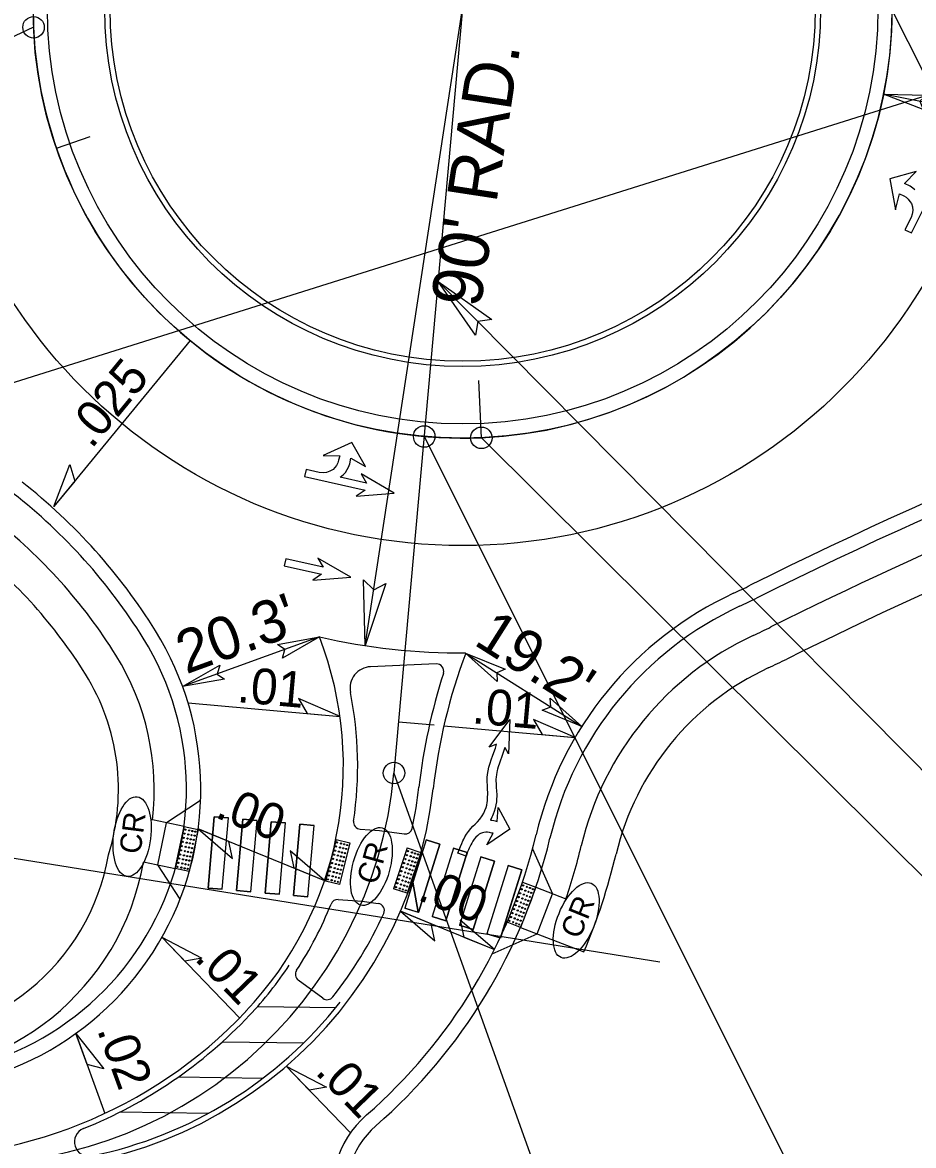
# Model space of a CAD drawing. Extents: x 2010838 to 2015151, y 441905 to 447792.
# Drawn here: x 2013126.8 to 2013251.3, y 444759.6 to 444916.5 of the extents above; entities that cross this region are included whole.
import ezdxf

# ---------------------------------------------------------------- set-up
doc = ezdxf.new("R2010")
doc.units = 0
for name, color, linetype in [('A-Wall-Abov', 7, 'Continuous'), ('A-Wall-Blow', 7, 'Continuous'), ('A-Wall-Comp', 7, 'Continuous'), ('C-Alignment Geometry', 7, 'Continuous'), ('C-Building', 7, 'Continuous'), ('C-CURB STOPS', 7, 'Continuous'), ('C-EOP 1', 7, 'Continuous'), ('C-Grave Plots', 7, 'Continuous'), ('CLRD', 7, 'Continuous'), ('DEED', 7, 'Continuous'), ('Default_10ft_LIDAR_Contou', 7, 'Continuous'), ('HATCH', 7, 'Continuous'), ('s-Existing Major', 7, 'Continuous'), ('S-Existing Minor', 7, 'Continuous'), ('S-overhead electric', 7, 'Continuous'), ('TEXT-LG', 7, 'Continuous'), ('TEXT-MED', 7, 'Continuous'), ('X3', 7, 'Continuous'), ('X4', 7, 'Continuous')]:
    doc.layers.add(name, color=color, linetype=linetype)

msp = doc.modelspace()

# ---------------------------------------------------------------- linework, layer by layer
at = {"layer": 'A-Wall-Abov'}
msp.add_lwpolyline([(2013251.45, 444893.1), (2013251.16, 444893.34), (2013250.77, 444893.6), (2013250.02, 444893.95), (2013251.63, 444895.67), (2013247.94, 444894.62), (2013248.76, 444890.3), (2013249.32, 444892.54), (2013249.89, 444892.23), (2013250.23, 444892.05), (2013250.53, 444891.79), (2013250.75, 444891.48), (2013250.97, 444891.16), (2013251.11, 444890.69), (2013251.14, 444890.19), (2013251.08, 444889.71), (2013250.92, 444889.2), (2013250.06, 444887.5), (2013250.96, 444887.06), (2013254.83, 444894.81)], dxfattribs=at)
for points in [[(2013166.18, 444853.06), (2013174.64, 444851.14), (2013173.42, 444850.31), (2013178.73, 444850.73), (2013174.12, 444853.4), (2013174.86, 444852.12), (2013171.18, 444852.95), (2013171.64, 444853.32), (2013171.92, 444853.62), (2013172.17, 444854.02), (2013172.33, 444854.36), (2013172.5, 444854.8), (2013172.66, 444855.61), (2013174.71, 444854.46), (2013172.81, 444857.79), (2013168.81, 444855.97), (2013171.11, 444855.96), (2013170.96, 444855.33), (2013170.86, 444854.96), (2013170.68, 444854.6), (2013170.43, 444854.31), (2013170.17, 444854.03), (2013169.75, 444853.78), (2013169.28, 444853.62), (2013168.79, 444853.57), (2013168.25, 444853.61), (2013166.41, 444854.03)], [(2013168.05, 444841.66), (2013168.78, 444840.38), (2013163.59, 444841.57), (2013163.36, 444840.59), (2013168.56, 444839.41), (2013167.35, 444838.57), (2013172.65, 444838.99)], [(2013194.89, 444819.09), (2013194.69, 444814.3), (2013194.2, 444815.17), (2013194.18, 444815.2), (2013193.73, 444813.95), (2013193.51, 444813.31), (2013193.41, 444813.01), (2013193.24, 444812.49), (2013193.15, 444812.18), (2013193.09, 444811.98), (2013192.99, 444811.44), (2013192.95, 444811.07), (2013192.93, 444810.8), (2013192.93, 444810.51), (2013192.94, 444810.18), (2013192.95, 444809.98), (2013192.96, 444809.68), (2013193.03, 444809.09), (2013193.05, 444808.66), (2013193.04, 444808.35), (2013193.03, 444808.05), (2013192.99, 444807.6), (2013192.93, 444807.21), (2013192.83, 444806.74), (2013192.7, 444806.28), (2013192.56, 444805.91), (2013192.45, 444805.64), (2013192.35, 444805.45), (2013192.15, 444805.07), (2013192.34, 444805.05), (2013192.63, 444805), (2013192.81, 444804.96), (2013193.1, 444804.89), (2013193.22, 444806.82), (2013194.87, 444803.8), (2013191.66, 444801.61), (2013192.52, 444803.22), (2013192.34, 444803.26), (2013192.03, 444803.33), (2013191.76, 444803.37), (2013191.51, 444803.38), (2013191.26, 444803.35), (2013191.05, 444803.3), (2013190.75, 444803.17), (2013190.59, 444803.08), (2013190.39, 444802.93), (2013190.1, 444802.66), (2013189.91, 444802.4), (2013189.72, 444802.11), (2013189.56, 444801.86), (2013189.43, 444801.62), (2013189.28, 444801.33), (2013189.19, 444801.14), (2013189.09, 444800.92), (2013188.98, 444800.65), (2013188.9, 444800.43), (2013188.81, 444800.17), (2013188.77, 444800.04), (2013187.61, 444800.45), (2013187.79, 444800.93), (2013187.97, 444801.37), (2013188.15, 444801.78), (2013188.32, 444802.16), (2013188.45, 444802.42), (2013188.6, 444802.72), (2013188.83, 444803.09), (2013189.11, 444803.49), (2013189.4, 444803.87), (2013189.72, 444804.2), (2013190.03, 444804.49), (2013190.36, 444804.84), (2013190.66, 444805.2), (2013191.01, 444805.68), (2013191.23, 444806.04), (2013191.4, 444806.39), (2013191.55, 444806.8), (2013191.65, 444807.16), (2013191.72, 444807.5), (2013191.75, 444807.74), (2013191.77, 444808.12), (2013191.78, 444808.81), (2013191.76, 444809.44), (2013191.73, 444810.01), (2013191.7, 444810.37), (2013191.69, 444810.55), (2013191.7, 444811.02), (2013191.74, 444811.45), (2013191.83, 444811.95), (2013191.95, 444812.46), (2013192.11, 444813), (2013192.27, 444813.48), (2013192.49, 444814.12), (2013192.85, 444815.12), (2013193.03, 444815.66), (2013192, 444815.26)]]:
    msp.add_lwpolyline(points, close=True, dxfattribs=at)
at = {"layer": 'A-Wall-Blow'}
for p, q in [((2013150.2, 444872.03), (2013131.16, 444848.84)), ((2013149.92, 444821.44), (2013171.15, 444819.53)), ((2013185.65, 444818.23), (2013203.98, 444816.58)), ((2013151.33, 444803.82), (2013168.99, 444796.64)), ((2013179.59, 444792.33), (2013192.71, 444786.99)), ((2013146.27, 444788.69), (2013157.12, 444777.44)), ((2013134.23, 444775.25), (2013138.31, 444764.1)), ((2013163.64, 444770.69), (2013172.61, 444761.39))]:
    msp.add_line(p, q, dxfattribs=at)
at = {"layer": 'A-Wall-Comp'}
for points in [[(2013131.16, 444848.84), (2013133.43, 444854.75), (2013134.1, 444852.42)], [(2013171.15, 444819.53), (2013165.35, 444822.06), (2013166.54, 444819.95)], [(2013203.98, 444816.58), (2013198.18, 444819.11), (2013199.37, 444817)], [(2013151.33, 444803.82), (2013156.14, 444799.71), (2013155.62, 444802.08)], [(2013168.99, 444796.64), (2013164.18, 444800.75), (2013164.7, 444798.38)], [(2013179.59, 444792.33), (2013184.39, 444788.21), (2013183.87, 444790.58)], [(2013192.71, 444786.99), (2013187.91, 444791.1), (2013188.43, 444788.73)], [(2013146.27, 444788.69), (2013151.87, 444785.76), (2013149.48, 444785.36)], [(2013134.23, 444775.25), (2013138.17, 444770.31), (2013135.82, 444770.91)], [(2013163.64, 444770.69), (2013169.25, 444767.76), (2013166.85, 444767.36)]]:
    msp.add_lwpolyline(points, close=True, dxfattribs=at)
at = {"layer": 'C-Alignment Geometry'}
for p, q in [((2013159.66, 444779.05), (2013170.58, 444778.91)), ((2013154.74, 444774.11), (2013166.1, 444773.97)), ((2013148.58, 444769.2), (2013160.41, 444769.04)), ((2013140.44, 444764.3), (2013152.83, 444764.14))]:
    msp.add_line(p, q, dxfattribs=at)
for centre, radius, start, end in [((2013121.62, 444812.65), 50.75, 316.6324, 326.7514), ((2013124.54, 444816.2), 59.25, 281.6024, 321.882), ((2013110.72, 444822.95), 65.75, 291.9588, 316.6324), ((2013136.05, 444760.12), 2, 111.9588, 281.6024)]:
    msp.add_arc(centre, radius, start, end, dxfattribs=at)
at = {"layer": 'C-Building'}
for p, q in [((2013131.54, 444898.89), (2013136.27, 444900.52)), ((2013179.34, 444818.8), (2013184.32, 444818.35))]:
    msp.add_line(p, q, dxfattribs=at)
at = {"layer": 'C-CURB STOPS'}
for p, q in [((2013184.6, 444826.87), (2013175.42, 444826.47)), ((2013173.97, 444803.79), (2013176.67, 444803.6)), ((2013176.67, 444803.6), (2013180.11, 444803.13)), ((2013170.9, 444793.97), (2013174.25, 444793.75)), ((2013174.25, 444793.75), (2013176.49, 444793.43)), ((2013168.77, 444780.18), (2013165.31, 444782.73))]:
    msp.add_line(p, q, dxfattribs=at)
msp.add_circle((2013188.28, 444918.4), 58, dxfattribs=at)
for centre, radius, start, end in [((2013184.64, 444825.87), 1, 342.1406, 92.4521), ((2013175.55, 444823.48), 3, 92.4521, 191.35), ((2013263.65, 444800.41), 82, 162.1406, 173.5264), ((2013121.62, 444812.65), 52, 351.464, 11.35), ((2013124.54, 444816.2), 58, 347.7647, 353.5264), ((2013174.04, 444804.79), 1, 171.464, 266.1176), ((2013180.24, 444804.12), 1, 262.0911, 347.7647), ((2013170.83, 444792.97), 1, 86.1176, 158.2062), ((2013121.62, 444812.65), 52, 326.6756, 338.2062), ((2013176.35, 444792.44), 1, 335.3711, 82.0911), ((2013124.54, 444816.2), 58, 321.8457, 335.3711), ((2013165.91, 444783.53), 1, 146.6756, 233.5385), ((2013169.36, 444780.98), 1, 233.5385, 321.8457)]:
    msp.add_arc(centre, radius, start, end, dxfattribs=at)
at = {"layer": 'C-EOP 1'}
msp.add_line((2013190.89, 444858.45), (2013190.54, 444866.45), dxfattribs=at)
at = {"layer": 'CLRD'}
msp.add_line((2013188.28, 444918.4), (2013178.69, 444811.64), dxfattribs=at)
for centre, start, end in [((2013188.28, 444918.4), 92.4922, 182.4922), ((2013188.28, 444918.4), 272.4922, 2.4922), ((2013188.28, 444918.4), 182.4922, 272.4922), ((2013118.93, 444817), 266.9102, 354.8697)]:
    msp.add_arc(centre, 60, start, end, dxfattribs=at)
at = {"layer": 'DEED'}
for radius in [50, 49.25]:
    msp.add_circle((2013188.28, 444918.4), radius, dxfattribs=at)
at = {"layer": 'Default_10ft_LIDAR_Contou'}
for p, q in [((2013248.28, 444918.14), (2013322.3, 444771.2)), ((2013128.34, 444915.79), (2012938.22, 444827.44)), ((2013184.86, 444880.3), (2013338.65, 444724.98)), ((2013182.91, 444858.64), (2013267.89, 444688.86)), ((2013190.89, 444858.45), (2013335.72, 444714.48)), ((2013178.69, 444811.64), (2013247.53, 444618.89))]:
    msp.add_line(p, q, dxfattribs=at)
for centre in [(2013128.34, 444915.79), (2013182.91, 444858.64), (2013190.89, 444858.45), (2013190.89, 444858.45), (2013178.69, 444811.64)]:
    msp.add_circle(centre, 1.5, dxfattribs=at)
at = {"layer": 'HATCH'}
for p, q in [((2013188.7, 444828.4), (2013204.92, 444818.13)), ((2013152.71, 444795.57), (2013153.58, 444805.53)), ((2013153.58, 444805.53), (2013152.72, 444795.57)), ((2013153.58, 444805.53), (2013155.57, 444805.36)), ((2013155.57, 444805.36), (2013153.58, 444805.53)), ((2013154.71, 444795.4), (2013155.57, 444805.36)), ((2013154.71, 444795.4), (2013155.57, 444805.36)), ((2013156.7, 444795.23), (2013157.56, 444805.19)), ((2013157.56, 444805.19), (2013156.7, 444795.23)), ((2013157.56, 444805.19), (2013159.56, 444805.01)), ((2013159.56, 444805.01), (2013157.56, 444805.19)), ((2013158.69, 444795.05), (2013159.56, 444805.01)), ((2013158.69, 444795.05), (2013159.56, 444805.01)), ((2013160.68, 444794.88), (2013161.55, 444804.84)), ((2013161.55, 444804.84), (2013160.68, 444794.88)), ((2013161.55, 444804.84), (2013163.54, 444804.67)), ((2013163.54, 444804.67), (2013161.55, 444804.84)), ((2013162.68, 444794.71), (2013163.54, 444804.67)), ((2013162.68, 444794.71), (2013163.54, 444804.67)), ((2013164.67, 444794.53), (2013165.53, 444804.5)), ((2013165.53, 444804.5), (2013164.67, 444794.53)), ((2013165.53, 444804.5), (2013167.53, 444804.32)), ((2013167.53, 444804.32), (2013165.53, 444804.5)), ((2013166.66, 444794.36), (2013167.53, 444804.32)), ((2013166.66, 444794.36), (2013167.53, 444804.32)), ((2013183.2, 444802.32), (2013180.21, 444792.78)), ((2013183.2, 444802.32), (2013181.34, 444796.38)), ((2013185.11, 444801.72), (2013182.11, 444792.18)), ((2013182.11, 444792.18), (2013185.11, 444801.72)), ((2013183.2, 444802.32), (2013185.11, 444801.72)), ((2013185.11, 444801.72), (2013183.2, 444802.32)), ((2013187.02, 444801.12), (2013184.02, 444791.58)), ((2013187.02, 444801.12), (2013184.03, 444791.6)), ((2013188.93, 444800.52), (2013185.93, 444790.98)), ((2013185.93, 444790.98), (2013188.93, 444800.52)), ((2013187.02, 444801.12), (2013188.93, 444800.52)), ((2013188.93, 444800.52), (2013187.02, 444801.12)), ((2013190.84, 444799.92), (2013187.84, 444790.38)), ((2013190.84, 444799.92), (2013187.84, 444790.38)), ((2013190.84, 444799.92), (2013192.74, 444799.33)), ((2013192.74, 444799.33), (2013190.84, 444799.92)), ((2013192.74, 444799.33), (2013189.75, 444789.78)), ((2013189.75, 444789.78), (2013192.74, 444799.33)), ((2013194.65, 444798.73), (2013191.66, 444789.19)), ((2013194.65, 444798.73), (2013191.66, 444789.19)), ((2013194.65, 444798.73), (2013196.56, 444798.13)), ((2013196.56, 444798.13), (2013194.65, 444798.73)), ((2013196.56, 444798.13), (2013193.56, 444788.59)), ((2013193.72, 444789.09), (2013196.56, 444798.13)), ((2013154.71, 444795.4), (2013152.72, 444795.57)), ((2013152.72, 444795.57), (2013154.71, 444795.4)), ((2013158.69, 444795.05), (2013156.7, 444795.23)), ((2013156.7, 444795.23), (2013158.69, 444795.05)), ((2013181.34, 444796.38), (2013180.21, 444792.78)), ((2013181.34, 444796.38), (2013182.06, 444792.2)), ((2013182.06, 444792.2), (2013181.34, 444796.38)), ((2013162.68, 444794.71), (2013160.68, 444794.88)), ((2013160.68, 444794.88), (2013162.68, 444794.71)), ((2013166.66, 444794.36), (2013164.67, 444794.53)), ((2013164.67, 444794.53), (2013166.66, 444794.36)), ((2013182.11, 444792.18), (2013180.21, 444792.78)), ((2013180.21, 444792.78), (2013182.06, 444792.2)), ((2013182.06, 444792.2), (2013182.11, 444792.18)), ((2013185.93, 444790.98), (2013184.03, 444791.6)), ((2013184.03, 444791.6), (2013185.93, 444790.98)), ((2013189.75, 444789.78), (2013187.84, 444790.38)), ((2013187.84, 444790.38), (2013189.75, 444789.78)), ((2013193.56, 444788.59), (2013191.66, 444789.19)), ((2013191.66, 444789.19), (2013193.5, 444788.61))]:
    msp.add_line(p, q, dxfattribs=at)
msp.add_circle((2013188.28, 444918.4), 75, dxfattribs=at)
msp.add_arc((2013125.58, 444820.42), 75, 334.9004, 335.3097, dxfattribs=at)
at = {"layer": 's-Existing Major'}
for points in [[(2013252.62, 444904.32), (2013247.08, 444906.47), (2013253.05, 444906.32), (2013252.12, 444905.45)], [(2013190.09, 444872.81), (2013184.86, 444880.3), (2013192.36, 444874.99), (2013190.42, 444874.68)], [(2013177.56, 444838.09), (2013174.66, 444829.43), (2013174.45, 444838.62), (2013175.86, 444837.24)], [(2013162.43, 444829.6), (2013168.27, 444830.65), (2013163.1, 444827.66), (2013163.45, 444828.89)], [(2013193.1, 444824.42), (2013188.7, 444828.4), (2013194.23, 444826.13), (2013193.04, 444825.65)], [(2013155.01, 444824.75), (2013149.17, 444823.7), (2013154.34, 444826.69), (2013153.99, 444825.46)], [(2013200.51, 444822.11), (2013204.92, 444818.13), (2013199.39, 444820.4), (2013200.58, 444820.88)]]:
    msp.add_lwpolyline(points, close=True, dxfattribs=at)
at = {"layer": 'S-Existing Minor'}
for p, q in [((2012728, 444741.11), (2013407.25, 444954.8)), ((2013174.66, 444829.43), (2013188.28, 444918.4)), ((2013264.72, 444902.89), (2013247.08, 444906.47)), ((2013168.27, 444830.65), (2013149.17, 444823.7)), ((2013188.7, 444828.4), (2013204.92, 444818.13))]:
    msp.add_line(p, q, dxfattribs=at)
at = {"layer": 'S-overhead electric'}
msp.add_circle((2013188.28, 444918.4), 60, dxfattribs=at)
for centre, radius, start, end in [((2013509.51, 444274.03), 630, 98.35841, 116.49713), ((2013077.42, 444789.28), 80, 31.8625, 51.9343), ((2013188.28, 444918.4), 90, 294.8702, 296.4971), ((2013247.16, 444791.38), 50, 114.8702, 166.5654), ((2013109.7, 444809.34), 42, 266.6924, 31.8625), ((2013121.62, 444812.65), 50, 316.6324, 21.0956), ((2013188.28, 444918.4), 90, 257.155, 270.2673), ((2013263.65, 444800.41), 80, 159.5249, 173.5264), ((2013124.54, 444816.2), 60, 266.9102, 353.5264), ((2013125.58, 444820.42), 75, 311.0732, 346.5651), ((2013110.72, 444822.95), 65, 266.9102, 316.6324), ((2013184.05, 444753.33), 14, 131.0732, 263.7653)]:
    msp.add_arc(centre, radius, start, end, dxfattribs=at)
at = {"layer": 'TEXT-LG'}
for p, q in [((2013151.67, 444807.8), (2013146.91, 444804.67)), ((2013149.36, 444804.16), (2013144.94, 444805.08)), ((2013145.68, 444798.8), (2013146.91, 444804.67)), ((2013149.37, 444804.16), (2013148.14, 444798.29)), ((2013148.14, 444798.29), (2013149.37, 444804.16)), ((2013149.37, 444804.16), (2013151.32, 444803.75)), ((2013151.32, 444803.75), (2013150.1, 444797.88)), ((2013170.59, 444802.37), (2013169.12, 444796.55)), ((2013170.59, 444802.37), (2013172.53, 444801.88)), ((2013172.53, 444801.88), (2013171.06, 444796.06)), ((2013180.54, 444801.17), (2013178.64, 444795.48)), ((2013180.54, 444801.17), (2013182.44, 444800.53)), ((2013182.44, 444800.53), (2013180.54, 444794.84)), ((2013198.04, 444801.06), (2013200.84, 444794.78)), ((2013148.14, 444798.28), (2013143.7, 444799.21)), ((2013148.81, 444794.03), (2013145.68, 444798.8)), ((2013150.1, 444797.88), (2013148.14, 444798.29)), ((2013171.06, 444796.06), (2013169.12, 444796.55)), ((2013180.54, 444794.84), (2013178.64, 444795.48)), ((2013196.63, 444796.39), (2013194.48, 444790.79)), ((2013198.49, 444795.68), (2013196.35, 444790.07)), ((2013196.63, 444796.39), (2013198.49, 444795.68)), ((2013198.49, 444795.68), (2013202.7, 444794.07)), ((2013198.69, 444789.18), (2013200.84, 444794.78)), ((2013196.35, 444790.07), (2013194.48, 444790.79)), ((2013192.4, 444786.37), (2013198.69, 444789.18)), ((2013196.35, 444790.07), (2013205.22, 444786.67))]:
    msp.add_line(p, q, dxfattribs=at)
for centre in [(2013149.42, 444803.17), (2013149.54, 444803.73), (2013149.96, 444803.06), (2013150.08, 444803.63), (2013150.53, 444803.53), (2013150.95, 444803.45), (2013149.05, 444801.43), (2013149.18, 444802.02), (2013149.3, 444802.58), (2013149.72, 444801.91), (2013149.84, 444802.48), (2013150.17, 444801.82), (2013150.29, 444802.38), (2013150.41, 444802.96), (2013150.59, 444801.74), (2013150.71, 444802.3), (2013150.84, 444802.89), (2013170.75, 444801.93), (2013171.29, 444801.8), (2013171.73, 444801.68), (2013172.15, 444801.58), (2013148.81, 444800.25), (2013148.93, 444800.84), (2013149.35, 444800.14), (2013149.48, 444800.73), (2013149.6, 444801.33), (2013149.8, 444800.04), (2013149.93, 444800.63), (2013150.05, 444801.23), (2013150.22, 444799.97), (2013150.35, 444800.55), (2013150.47, 444801.15), (2013170.32, 444800.23), (2013170.46, 444800.79), (2013170.61, 444801.37), (2013170.85, 444800.11), (2013171, 444800.66), (2013171.15, 444801.24), (2013171.3, 444799.99), (2013171.44, 444800.54), (2013171.59, 444801.12), (2013171.72, 444799.89), (2013171.86, 444800.45), (2013172.01, 444801.03), (2013180.48, 444800.18), (2013180.66, 444800.72), (2013181.01, 444800.01), (2013181.19, 444800.55), (2013181.44, 444799.86), (2013181.62, 444800.4), (2013182.04, 444800.27), (2013148.45, 444798.54), (2013148.57, 444799.1), (2013148.69, 444799.69), (2013148.99, 444798.43), (2013149.11, 444799), (2013149.23, 444799.58), (2013149.44, 444798.33), (2013149.56, 444798.9), (2013149.68, 444799.48), (2013149.98, 444798.82), (2013150.11, 444799.41), (2013169.87, 444798.48), (2013170.02, 444799.06), (2013170.17, 444799.65), (2013170.41, 444798.35), (2013170.56, 444798.93), (2013170.71, 444799.52), (2013171, 444798.81), (2013171.15, 444799.41), (2013171.42, 444798.72), (2013171.57, 444799.31), (2013179.91, 444798.49), (2013180.1, 444799.06), (2013180.29, 444799.61), (2013180.44, 444798.33), (2013180.63, 444798.9), (2013180.81, 444799.44), (2013181.07, 444798.74), (2013181.25, 444799.29), (2013181.48, 444798.62), (2013181.66, 444799.16), (2013181.85, 444799.73), (2013149.86, 444798.26), (2013169.44, 444796.79), (2013169.58, 444797.34), (2013169.73, 444797.92), (2013170.12, 444797.21), (2013170.27, 444797.8), (2013170.56, 444797.1), (2013170.71, 444797.68), (2013170.85, 444798.23), (2013170.98, 444797), (2013171.13, 444797.58), (2013171.27, 444798.14), (2013179.35, 444796.8), (2013179.53, 444797.35), (2013179.72, 444797.92), (2013180.06, 444797.18), (2013180.25, 444797.75), (2013180.49, 444797.03), (2013180.68, 444797.6), (2013180.87, 444798.18), (2013180.9, 444796.9), (2013181.09, 444797.47), (2013181.28, 444798.05), (2013169.98, 444796.66), (2013170.42, 444796.54), (2013170.84, 444796.44), (2013178.97, 444795.69), (2013179.15, 444796.24), (2013179.5, 444795.52), (2013179.68, 444796.07), (2013179.87, 444796.64), (2013179.93, 444795.37), (2013180.12, 444795.92), (2013180.31, 444796.48), (2013180.34, 444795.25), (2013180.53, 444795.79), (2013180.72, 444796.36), (2013196.52, 444795.4), (2013196.73, 444795.94), (2013197.04, 444795.21), (2013197.25, 444795.75), (2013197.68, 444795.58), (2013198.08, 444795.43), (2013195.88, 444793.75), (2013196.1, 444794.31), (2013196.3, 444794.84), (2013196.62, 444794.12), (2013196.82, 444794.65), (2013197.05, 444793.95), (2013197.25, 444794.48), (2013197.45, 444793.8), (2013197.47, 444795.04), (2013197.66, 444794.34), (2013197.87, 444794.9), (2013195.24, 444792.08), (2013195.45, 444792.62), (2013195.67, 444793.18), (2013195.97, 444792.43), (2013196.19, 444792.99), (2013196.4, 444793.56), (2013196.4, 444792.26), (2013196.61, 444792.82), (2013196.8, 444792.11), (2013196.83, 444793.39), (2013197.02, 444792.67), (2013197.23, 444793.24), (2013194.82, 444790.99), (2013195.03, 444791.52), (2013195.34, 444790.8), (2013195.55, 444791.33), (2013195.76, 444791.89), (2013195.77, 444790.63), (2013195.97, 444791.16), (2013196.17, 444790.48), (2013196.19, 444791.72), (2013196.38, 444791.02), (2013196.6, 444791.58)]:
    msp.add_circle(centre, 0.0869, dxfattribs=at)
for centre, radius, start, end in [((2013509.51, 444274.03), 618.5, 101.90818, 116.49713), ((2013509.51, 444274.03), 623.5, 109.62496, 116.49713), ((2013509.51, 444274.03), 623.5, 109.62496, 116.49713), ((2013077.42, 444789.28), 73.5, 31.8625, 51.9343), ((2013077.42, 444789.28), 68.5, 31.8625, 51.9343), ((2013188.28, 444918.4), 96.5, 294.8702, 296.4971), ((2013247.16, 444791.38), 43.5, 114.8702, 166.5654), ((2013109.7, 444809.34), 35.5, 353.0961, 31.8625), ((2013188.28, 444918.4), 101.5, 294.8702, 296.4971), ((2013109.7, 444809.34), 30.5, 342.6037, 31.8625), ((2013247.16, 444791.38), 38.5, 114.8702, 166.5654), ((2013108.27, 444805.46), 30.98, 267.8497, 350.2796), ((2013125.58, 444820.42), 81.5, 341.1323, 346.5651), ((2013125.58, 444820.42), 86.5, 337.0368, 346.5651), ((2013108.27, 444805.46), 35.98, 267.8497, 349.9973)]:
    msp.add_arc(centre, radius, start, end, dxfattribs=at)
at = {"layer": 'TEXT-MED'}
for centre, radius, start, end in [((2013509.51, 444274.03), 628, 98.35841, 116.49713), ((2013077.42, 444789.28), 78, 31.8625, 51.9343), ((2013188.28, 444918.4), 92, 294.8702, 296.4971), ((2013247.16, 444791.38), 48, 114.8702, 166.5654), ((2013109.7, 444809.34), 40, 266.6924, 31.8625), ((2013125.58, 444820.42), 77, 311.0732, 346.5651), ((2013184.05, 444753.33), 12, 131.0732, 263.7653)]:
    msp.add_arc(centre, radius, start, end, dxfattribs=at)
at = {"layer": 'X3'}
msp.add_line((2013215.8, 444785.23), (2013122.55, 444800.21), dxfattribs=at)
at = {"layer": 'X4'}
for centre, major_axis in [((2013142.11, 444802.76), (0.71, 5.56)), ((2013175.53, 444798.59), (1.51, 5.4)), ((2013204.14, 444791.06), (2.11, 5.19))]:
    msp.add_ellipse(centre, major_axis=major_axis, ratio=0.462467, dxfattribs=at)

# ---------------------------------------------------------------- texts
at = {"layer": 'A-Wall-Blow'}
for s, rotation, p in [('.025', 50.6088, (2013136.44, 444856.79)), ('.01', 354.8697, (2013156.67, 444821.56)), ('.01', 354.8697, (2013189.5, 444818.61)), ('.00', 337.8625, (2013153.55, 444805.5)), ('.00', 337.8625, (2013181.81, 444794.01)), ('.01', 313.9893, (2013150.68, 444785.65)), ('.02', 290.116, (2013137.17, 444775.79)), ('.01', 313.9893, (2013167.53, 444769.78))]:
    msp.add_text(s, height=5, rotation=rotation, dxfattribs=at).set_placement(p)
at = {"layer": 'C-Grave Plots'}
for s, height, rotation, p in [("90' RAD.", 7, 81.2979, (2013190.73, 444876.45)), ("20.3'", 6, 19.9868, (2013149.65, 444825.4)), ("19.2'", 6, 327.6569, (2013189.66, 444829.67))]:
    msp.add_text(s, height=height, rotation=rotation, dxfattribs=at).set_placement(p)
at = {"layer": 'X4'}
for rotation, p in [(82.7699, (2013143.28, 444800.23)), (74.35, (2013176.32, 444795.92)), (67.8566, (2013204.62, 444788.32))]:
    msp.add_text('CR', height=3, rotation=rotation, dxfattribs=at).set_placement(p)

doc.saveas('drawing.dxf')
